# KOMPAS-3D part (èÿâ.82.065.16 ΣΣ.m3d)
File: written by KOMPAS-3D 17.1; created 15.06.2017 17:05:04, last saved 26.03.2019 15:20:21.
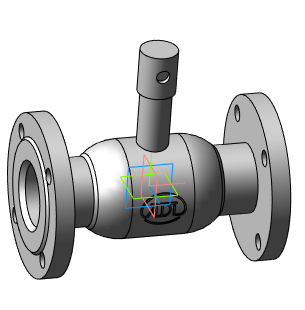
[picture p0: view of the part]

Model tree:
1. Операция без истории:2  (labels: Сталь 20  ГОСТ 1050-88)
